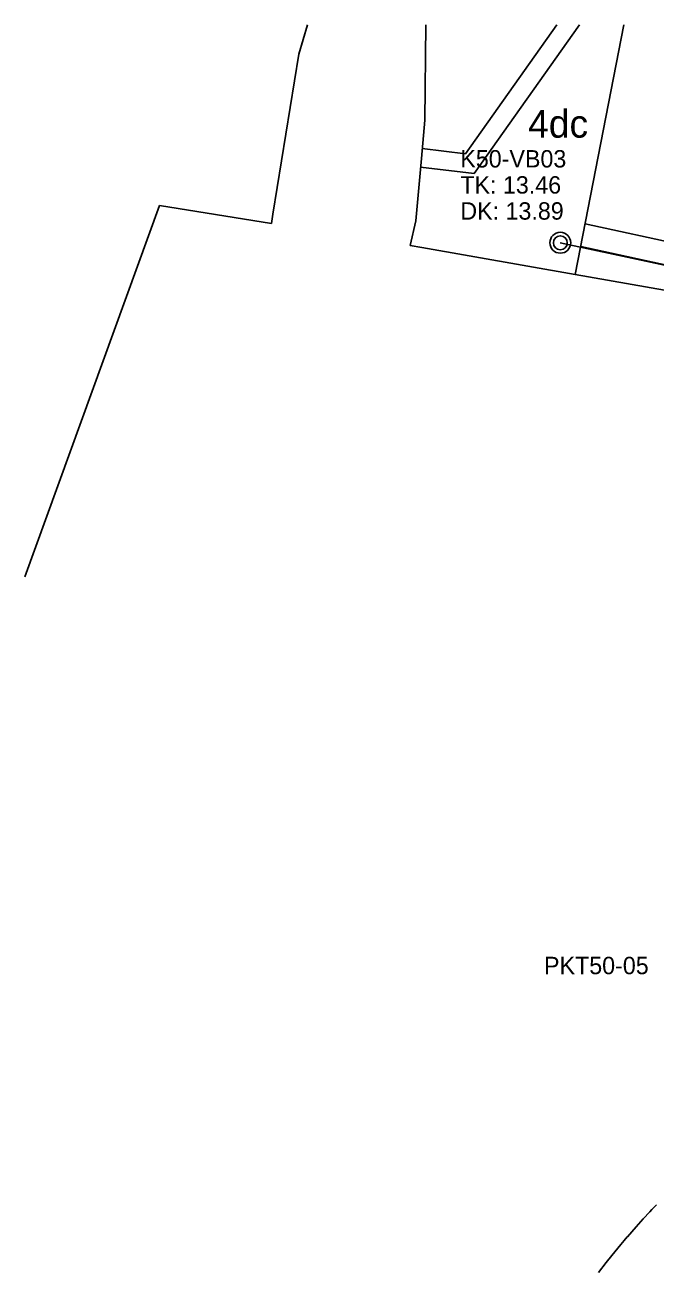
# Model space of a CAD drawing. Extents: x 702630 to 703245, y 6205279 to 6205714.
# Drawn here: x 702630.1 to 702766.1, y 6205441.3 to 6205710 of the extents above; entities that cross this region are included whole.
import ezdxf

# ---------------------------------------------------------------- set-up
doc = ezdxf.new("R2010")
doc.units = 0
for name, color, linetype in [('Brønd', 7, 'Continuous'), ('Brønd_Text', 7, 'Continuous'), ('Dæksel', 7, 'Continuous'), ('Matrikelnummer', 7, 'Continuous'), ('Matrikelnummer punkt', 7, 'Continuous'), ('Matrikelskel Almindeligt', 7, 'Continuous'), ('Optaget vej', 7, 'Continuous'), ('Punkt_Text', 7, 'Continuous'), ('Trykledning', 7, 'Continuous')]:
    doc.layers.add(name, color=color, linetype=linetype)

msp = doc.modelspace()

# ---------------------------------------------------------------- linework, layer by layer
at = {"layer": 'Brønd'}
msp.add_line((702745.65, 6205663.03), (702745.65, 6205663.03), dxfattribs=at)
msp.add_circle((702745.65, 6205663.03), 2.25, dxfattribs=at)
at = {"layer": 'Dæksel'}
msp.add_line((702745.65, 6205663.03), (702745.65, 6205663.03), dxfattribs=at)
msp.add_circle((702745.65, 6205663.03), 1.5, dxfattribs=at)
at = {"layer": 'Matrikelnummer punkt'}
msp.add_line((702743.44, 6205688.69), (702743.44, 6205688.69), dxfattribs=at)
at = {"layer": 'Matrikelskel Almindeligt'}
for p, q in [((702689.27, 6205703.7), (702691.14, 6205710)), ((702716.61, 6205710), (702716.43, 6205689.44)), ((702759.38, 6205710), (702748.87, 6205656.2)), ((702683.66, 6205669.16), (702689.27, 6205703.7)), ((702716.43, 6205689.44), (702715.68, 6205681.18)), ((702715.68, 6205681.18), (702714.46, 6205667.76)), ((702630.14, 6205590.96), (702659.18, 6205671.03)), ((702659.18, 6205671.03), (702683.34, 6205667.18)), ((702683.34, 6205667.18), (702683.66, 6205669.16)), ((702714.46, 6205667.76), (702713.24, 6205662.45)), ((702713.24, 6205662.45), (702715.74, 6205662.01)), ((702748.87, 6205656.2), (702715.74, 6205662.01)), ((702748.87, 6205656.2), (702795.76, 6205648))]:
    msp.add_line(p, q, dxfattribs=at)
at = {"layer": 'Optaget vej'}
for p, q in [((702725.2, 6205682.22), (702744.91, 6205710)), ((702749.82, 6205710), (702727.08, 6205677.97)), ((702725.2, 6205682.22), (702715.88, 6205683.32)), ((702727.08, 6205677.97), (702715.52, 6205679.33)), ((702790.77, 6205658.47), (702751, 6205667.12)), ((702789.81, 6205653.57), (702750.05, 6205662.21))]:
    msp.add_line(p, q, dxfattribs=at)
msp.add_lwpolyline([(702766.37, 6205455.59), (702765.39, 6205454.56), (702764.94, 6205454.08), (702763.56, 6205452.59), (702762, 6205450.85), (702760.11, 6205448.68), (702760.1, 6205448.67), (702759.42, 6205447.88), (702758.72, 6205447.04), (702756.77, 6205444.66), (702755.56, 6205443.13), (702753.89, 6205440.96)], dxfattribs=at)
at = {"layer": 'Trykledning'}
msp.add_lwpolyline([(702745.65, 6205663.03), (702800.04, 6205651.38)], dxfattribs=at)

# ---------------------------------------------------------------- texts
at = {"layer": 'Brønd_Text'}
for s, p in [('K50-VB03', (702724.08, 6205679.26)), ('TK: 13.46', (702724.08, 6205673.63)), ('DK: 13.89', (702724.08, 6205668.01))]:
    msp.add_text(s, height=3.75, dxfattribs=at).set_placement(p)
at = {"layer": 'Matrikelnummer'}
msp.add_text('4dc', height=6, dxfattribs=at).set_placement((702738.71, 6205685.69))
at = {"layer": 'Punkt_Text'}
msp.add_text('PKT50-05', height=3.75, dxfattribs=at).set_placement((702742.14, 6205505.31))

doc.saveas('drawing.dxf')
